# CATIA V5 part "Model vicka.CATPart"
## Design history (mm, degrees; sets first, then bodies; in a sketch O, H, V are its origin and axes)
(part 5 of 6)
    point P12 (-34.2109, 50.056)
    point P13 (-34.2607, 53.422)
    line L7 (-33.1167, 50.4591) -> (-33.1655, 53.754)
    point P15 (-33.1655, 53.754)
    line L8 (-22.1725, 60.0696) -> (-29.5056, 61.7557)
    point P16 (-29.5056, 61.7557)
    reference projected arc E12 centre (-31.265, 66.4359) radius 2 from (-32.3394, 64.749) to (-30.4134, 64.6263) ccw from edge [face of Fillet6 | face of Pad9]
    line L9 (-25.628, 55.9198) -> (-29.8107, 56.8816)
    point P17 (-25.628, 55.9198)
    point P18 (-29.8107, 56.8816)
    line L10 (-26.462, 54.9829) -> (-30.4107, 55.8909)
    point P20 (-30.4107, 55.8909)
    offset circle E13 centre (38.2049, 58.0324) radius 6.5 from edge [face of Pad47 | face of Hole7]
    offset arc E14 centre (38.2049, 58.0324) radius 6.5 from (38.8325, 51.5627) to (42.98, 53.6223) ccw from edge [face of Pad47 | face of Hole7]
    offset arc E15 centre (38.2049, 58.0324) radius 6.5 from (31.8341, 59.3221) to (32.6578, 54.6442) ccw from edge [face of Pad47 | face of Hole7]
    offset arc E16 centre (38.2049, 58.0324) radius 6.5 from (33.3151, 53.7499) to (37.7228, 51.5503) ccw from edge [face of Pad47 | face of Hole7]
    point P21 (27.2709, 56.8287)
    line L11 (27.2709, 56.8287) -> (28.9397, 54.6348)
    point P22 (28.9397, 54.6348)
    arc A2 centre (44.0622, 66.1374) radius 19 from (28.9397, 54.6348) to (30.1028, 53.2481) ccw
    point P24 (38.2983, 48.0328)
    line L12 (39.3947, 47.6838) -> (44.0557, 46.1999)
    point P25 (44.0557, 46.1999)
    reference projected arc E17 centre (34.2145, 64.9661) radius 2 from (33.2826, 63.1965) to (35.2121, 63.2327) ccw from edge [face of Fillet5 | face of Pad9]
    reference projected point E18 (38.2049, 58.0324) from Sketch44.P4
    reference projected arc E19 centre (0, 0) radius 71.425 from (68.6555, 19.6964) to (44.8942, 55.5522) ccw from edge [face of Pad1 from Sketch1.A1 | face of Pad9]
    line L13 (27.2709, 56.8287) -> (31.8341, 59.3221)
    point P26 (27.2709, 56.8287)
    point P27 (31.8341, 59.3221)
    line L14 (30.1028, 53.2481) -> (32.6578, 54.6442)
    point P29 (32.6578, 54.6442)
    line L15 (30.9032, 52.4319) -> (33.3151, 53.7499)
    point P30 (30.9032, 52.4319)
    point P31 (33.3151, 53.7499)
    line L16 (44.0557, 46.1999) -> (42.98, 53.6223)
    point P32 (42.98, 53.6223)
    line L17 (39.3947, 47.6838) -> (38.8325, 51.5627)
    point P34 (38.8325, 51.5627)
    line L18 (38.2294, 48.0549) -> (37.7228, 51.5503)
    point P35 (38.2294, 48.0549)
    point P36 (37.7228, 51.5503)
    arc A3 centre (44.0622, 66.1374) radius 19 from (30.9032, 52.4319) to (38.2294, 48.0549) ccw
    offset circle E24 centre (70.2785, -7.2128) radius 6.5 from edge [face of Pad47 | face of Hole12]
    offset arc E25 centre (70.2785, -7.2128) radius 6.5 from (64.3366, -9.8479) to (66.7122, -12.6471) ccw from edge [face of Pad47 | face of Hole12]
    offset arc E26 centre (70.2785, -7.2128) radius 6.5 from (63.9138, -5.8934) to (63.9722, -8.788) ccw from edge [face of Pad47 | face of Hole12]
    offset arc E27 centre (70.2785, -7.2128) radius 6.5 from (67.6327, -1.2757) to (64.2286, -4.8361) ccw from edge [face of Pad47 | face of Hole12]
    point P37 (64.4337, -12.9642)
    arc A4 centre (42.8563, -15.9675) radius 21.7854 from (64.4337, -12.9642) to (63.7868, -9.9244) ccw
    point P38 (42.8563, -15.9675)
    point P39 (63.627, -9.3961)
    arc A5 centre (81.742, -3.6649) radius 19 from (63.4656, -8.8585) to (62.884, -5.9837) cw
    point P41 (62.884, -5.9837)
    line L19 (62.884, -5.9837) -> (62.8445, -5.662)
    point P42 (62.1594, -0.0909)
    reference projected point E28 (70.2785, -7.2128) from Sketch44.P3
    reference projected line E29 (70.95, 8.2236) -> (75.4588, -5.0305) from edge [face of Pad47 | face of Pad6 from Sketch12.L1]
    line L20 (64.4337, -12.9642) -> (66.7122, -12.6471)
    point P43 (66.7122, -12.6471)
    line L21 (62.7023, -4.5057) -> (64.2286, -4.8361)
    point P44 (62.7023, -4.5057)
    line L22 (62.1594, -0.0909) -> (67.6327, -1.2757)
    point P46 (67.6327, -1.2757)
    line L23 (63.7868, -9.9244) -> (64.3366, -9.8479)
    point P48 (64.3366, -9.8479)
    line L24 (63.4656, -8.8585) -> (63.9722, -8.788)
    point P49 (63.4656, -8.8585)
    point P50 (63.9957, -8.7847)
    line L25 (63.9138, -5.8934) -> (62.8473, -5.6626)
    point P51 (63.9138, -5.8934)
    point P52 (62.8473, -5.6626)
    point P53 (63.9722, -8.788)
    line L26 (62.8473, -5.6626) -> (62.8445, -5.662)
    line L27 (62.7023, -4.5057) -> (62.1594, -0.0909)
    offset circle E30 centre (26.45, -66.45) radius 6.8 from edge [face of Pad47 | face of Hole11]
    offset arc E31 centre (26.45, -66.45) radius 6.8 from (26.3, -59.6517) to (21.6, -61.6837) ccw from edge [face of Pad47 | face of Hole11]
    offset arc E32 centre (26.45, -66.45) radius 6.8 from (32.3, -62.9834) to (27.3, -59.7033) ccw from edge [face of Pad47 | face of Hole11]
    line L28 (21.6, -61.6837) -> (21.6, -48.25)
    point P55 (21.6, -61.6837)
    point P56 (21.6, -48.25)
    line L29 (26.3, -59.6517) -> (26.3, -50.9964)
    point P57 (26.3, -59.6517)
    line L30 (27.3, -59.7033) -> (27.3, -51.4614)
    point P58 (27.3, -59.7033)
    line L31 (32.3, -62.9834) -> (32.3, -53.25)
    point P59 (32.3, -62.9834)
    point P60 (32.3, -53.25)
    reference projected line E33 (19.7, -73.2) -> (19.7, -54.5084) from edge [face of Pad47 | face of Pad3]
    point P61 (21.6, -48.25)
    arc A6 centre (41.5548, -19.4958) radius 35 from (21.6, -48.25) to (26.3, -50.9964) ccw
    point P63 (32.3, -53.25)
    point P64 (27.3, -51.4614)
    arc A7 centre (41.5548, -19.4958) radius 35 from (27.3, -51.4614) to (32.3, -53.25) ccw
    point P66 (63.9722, -8.788)
    distance P1 E3 = 6.7
    distance P1 E1 = 4
    distance P2 E3 = 3.6149
    length L1 = 4.2829
    radius A1 = 19
    distance E4 A1 = 3
    distance P6 E8 = 17.5
    distance P10 E8 = 19.3953
    distance P7 E9 = 11.2328
    distance P9 E10 H = 9.735
    distance P9 E10 V = 3.7831
    distance P11 E11 = 5
    distance L6 L5 = 4.4
    distance L7 L6 = 1.1
    distance P16 E12 = 3
    distance P17 P10 = 5.4
    distance L10 L9 = 1.1
    distance P17 P9 = 0.2
    radius A2 = 19
    distance P22 E17 = 9.6
    distance P21 E18 = 11
    distance P21 E19 = 8.3916
    distance E18 P25 = 13.2
    distance A2 E18 = 9
    distance P24 E18 = 10
    length L13 = 5.2
    distance P26 P21 = 0
    distance L14 L13 = 4.5
    distance L14 L15 = 1.1
    length L16 = 7.5
    distance L17 L16 = 4.4
    distance L18 L17 = 1.1
    length L12 = 4.8915
    radius A5 = 19
    distance A5 E28 = 7
    distance P42 E28 = 10.8
    distance P42 E29 = 11
    distance E28 P37 = 8.2
    distance P37 E3 = 5.7
    distance P39 E28 = 7.0006
    distance E28 P41 = 7.4959
    distance L23 L20 = 3.1
    distance L24 L23 = 1.1
    length L22 = 5.6
    distance L22 L21 = 4.2
    distance L25 L21 = 1.1
    radius A4 = 21.7854
    distance L28 E33 = 1.9
    distance L29 L28 = 4.7
    distance L30 L29 = 1
    distance L30 L31 = 5
    radius A6 = 35
    distance P60 E30 V = 20
    distance P61 P56 = 0
    distance E30 P56 V = 25
    distance P49 P50 = 0.5353
    coincidence: L2 P2, L1 P3, E1 P4, E1 P5, P11 E4, P12 A1, P13 E4, P15 E4, P16 E4, P17 A1, P18 E4, P20 E4, P26 L11, P27 E13, P29 E13, P30 A2, P31 E13, P32 E13, P34 E13, P35 A2, P36 E13, A2 A3, L20 P38, P43 E24, P44 L19, P46 E24, P48 E24, P51 E24, P52 A5, L24 P53, L19 L27, P55 E30, P57 E30, P58 E30, P59 E30, P63 P60, A6 P64, A6 A7, E24 P66, P5 P3, P4 P2, P53 P66
    tangency: A1 L3, L4 A1, A2 L11, L12 A2, A5 A4, L19 A5
    parallelism: L9 L8, L26 L25
    vertical: L28 V, L29 V, L30 V, L31 V
  Sketch120 on face of Pad47, origin (1.6, 0, 0), H (0, 1, 0), V (0, 0, 1)
    offset circle E1 centre (-26.2, -66.08) radius 6.6 from edge [face of Pad47 | face of Hole10]
    offset arc E2 centre (-26.2, -66.08) radius 6.6 from (-21.5, -61.4465) to (-25.4, -59.5287) ccw from edge [face of Pad47 | face of Hole10]
    offset arc E3 centre (-26.2, -66.08) radius 6.6 from (-26.6, -59.4922) to (-31.4, -62.0156) ccw from edge [face of Pad47 | face of Hole10]
    line L1 (-21.5, -61.4465) -> (-21.5, -52.9184)
    point P1 (-21.5, -61.4465)
    point P2 (-21.5, -52.9184)
    line L2 (-25.4, -59.5287) -> (-25.4, -55.9259)
    point P3 (-25.4, -59.5287)
    point P4 (-25.4, -55.9259)
    line L3 (-26.6, -59.4922) -> (-26.6, -56.8341)
    point P5 (-26.6, -59.4922)
    point P6 (-26.6, -56.8341)
    line L4 (-31.4, -62.0156) -> (-31.4, -58.0651)
    point P7 (-31.4, -62.0156)
    point P8 (-31.4, -58.0651)
    reference projected point E4 (-33.6, -68.8429) from vertex [face of Pocket3 | face of Pad5 from Sketch7.A1 | face of Pad47]
    reference projected line E5 (-19.7, -52.2166) -> (-19.7, -73.2) from edge [face of Pad47 | face of Pad2]
    arc A1 centre (-31.4067, -48.0651) radius 10 from (-31.4, -58.0651) to (-26.6, -56.8341) ccw
    arc A2 centre (-33.1042, -41.9028) radius 16 from (-25.4, -55.9259) to (-21.5, -52.9184) ccw
    distance E4 P8 = 11
    distance P6 E4 = 13.9
    distance P4 E4 = 15.3
    distance P2 E4 = 20
    distance L1 E5 = 1.8
    distance L2 L1 = 3.9
    distance L3 L2 = 1.2
    distance L4 L3 = 4.8
    radius A1 = 10
    radius A2 = 16
    coincidence: P1 E1, P3 E1, P5 E1, P7 E1
    vertical: L1 V, L2 V, L3 V, L4 V
  Pocket38: profile Sketch119, direction (-1, 0, 0), length 2.3
  Pocket39: profile Sketch120, direction (-1, 0, 0), length 2.3
  Sketch121 on face of Pad47, origin (1.6, 0, 0), H (0, 1, 0), V (0, 0, 1)
    offset arc E1 centre (-38.7, -63.15) radius 8 from (-30.7061, -62.8381) to (-43.1517, -56.503) ccw from edge [face of Pad47 | face of Pad10]
    offset arc E2 centre (-38.7, -63.15) radius 8 from (-31.4, -59.8774) to (-42.9711, -56.3856) ccw from edge [face of Pad47 | face of Pad10]
    arc A1 centre (-38.7, -63.15) radius 10.3 from (-29.8161, -57.9378) to (-43.2605, -53.9147) ccw
    construction line L1 (-30.7061, -62.8381) -> (-28.4085, -62.7129)
    construction line L2 (-43.1517, -56.503) -> (-44.4316, -54.592)
    offset line E3 (-42.7198, -56.7539) -> (-43.7073, -55.3064) from edge [face of Pad47 | face of Pad4 from Sketch6.L2]
    offset line E4 (-42.9711, -56.3856) -> (-43.7073, -55.3064) from edge [face of Pad47 | face of Pad4 from Sketch6.L2]
    offset arc E5 centre (-44.9464, -56.1518) radius 1.5 from (-43.7073, -55.3064) to (-44.0091, -54.9808) ccw from edge [face of Fillet2 | face of Pad47]
    point P9 (-41.8074, -54.0102)
    offset arc E6 centre (0, 0) radius 70.425 from (-70.1352, 6.382) to (-44.0091, -54.9808) ccw from edge [face of Pad1 from Sketch1.A1 | face of Pad47]
    offset arc E7 centre (0, 0) radius 69.125 from (-68.8406, 6.2642) to (-43.1967, -53.9658) ccw from edge [face of Pad1 from Sketch1.A1 | face of Pad47]
    offset arc E8 centre (0, 0) radius 69.125 from (-68.8406, 6.2642) to (-43.2605, -53.9147) ccw from edge [face of Pad1 from Sketch1.A1 | face of Pad47]
    arc A2 centre (-69.4879, 6.3231) radius 0.65 from (-70.1352, 6.382) to (-68.8406, 6.2642) cw
    point P15 (-43.2605, -53.9147)
    point P16 (-42.9711, -56.3856)
    point P17 (-42.9711, -56.3856)
    projected line E9 (-31.4, -58.0651) -> (-31.4, -62.0156) from edge [face of Pad47 | face of Pocket39 from Sketch120.L4]
    projected line E10 (-31.4, -58.0651) -> (-31.4, -59.8774) from edge [face of Pad47 | face of Pocket39 from Sketch120.L4]
    projected arc E11 centre (-31.4067, -48.0651) radius 10 from (-31.4, -58.0651) to (-26.6, -56.8341) ccw from edge [face of Pad47 | face of Pocket39 from Sketch120.A1]
    projected arc E12 centre (-31.4067, -48.0651) radius 10 from (-31.4, -58.0651) to (-29.8161, -57.9378) ccw from edge [face of Pad47 | face of Pocket39 from Sketch120.A1]
    point P22 (-29.8161, -57.9378)
    point P23 (-31.4, -59.8774)
    point P24 (-31.4, -59.8774)
    point P25 (-29.8161, -57.9378)
    point P26 (-65.1735, 18.7249)
    line L3 (-65.1735, 18.7249) -> (-59.997, 26.0872)
    arc A3 centre (-96.8086, 51.9698) radius 45 from (-59.997, 26.0872) to (-54.8919, 35.5993) ccw
    point P29 (-54.8919, 35.5993)
    line L4 (-54.8919, 35.5993) -> (-38.6712, 54.0939)
    point P30 (-38.6712, 54.0939)
    reference projected point E13 (-65.1735, 18.7249) from vertex [face of Pocket38 from Sketch119.L2 | face of Pocket38 from Sketch119.E2 | face of Pad47]
    reference projected point E14 (-38.6712, 54.0939) from vertex [face of Pocket38 from Sketch119.L5 | face of Pocket38 from Sketch119.E7 | face of Pad47]
    reference projected circle E15 centre (0, 0) radius 71.425 from edge [face of Pad1 from Sketch1.A1 | face of Pad47]
    line L5 (-61.291, 20.8391) -> (-58.3937, 24.9599)
    point P32 (-58.3937, 24.9599)
    construction line L6 (-65.1735, 18.7249) -> (-63.5702, 17.5975)
    construction line L7 (-59.997, 26.0872) -> (-58.3937, 24.9599)
    arc A4 centre (-95.2052, 50.8425) radius 45 from (-58.3937, 24.9599) to (-54.7989, 31.0351) ccw
    point P33 (-58.3937, 24.9599)
    point P34 (-54.7989, 31.0351)
    point P35 (-58.3937, 24.9599)
    line L8 (-51.7449, 36.1998) -> (-38.6277, 51.1559)
    construction line L9 (-54.8919, 35.5993) -> (-53.4108, 34.3004)
    construction line L10 (-38.6712, 54.0939) -> (-37.1901, 52.7949)
    line L11 (-54.7989, 31.0351) -> (-51.7449, 36.1998)
    reference projected arc E16 centre (-68.2522, 13.0002) radius 6.5 from (-63.1114, 16.9779) to (-65.1735, 18.7249) ccw from edge [face of Pad47 | face of Pocket38 from Sketch119.E2]
    projected line E17 (-61.2757, 20.8474) -> (-65.1735, 18.7249) from edge [face of Pad47 | face of Pocket38 from Sketch119.L2]
    projected line E18 (-61.291, 20.8391) -> (-65.1735, 18.7249) from edge [face of Pad47 | face of Pocket38 from Sketch119.L2]
    projected line E19 (-38.6712, 54.0939) -> (-38.5897, 48.5938) from edge [face of Pad47 | face of Pocket38 from Sketch119.L5]
    projected line E20 (-38.6712, 54.0939) -> (-38.6277, 51.1559) from edge [face of Pad47 | face of Pocket38 from Sketch119.L5]
    point P43 (-38.6277, 51.1559)
    point P44 (-61.291, 20.8391)
    point P45 (4.5944, 65.5788)
    line L12 (4.5944, 65.5788) -> (-13.3822, 66.4964)
    arc A5 centre (-13.9429, 55.5107) radius 11 from (-13.3822, 66.4964) to (-17.5476, 65.9033) ccw
    line L13 (-17.5476, 65.9033) -> (-29.5056, 61.7557)
    point P49 (-29.5056, 61.7557)
    projected line E21 (-22.1725, 60.0696) -> (-29.5056, 61.7557) from edge [face of Pad47 | face of Pocket38 from Sketch119.L8]
    projected line E22 (-26.5819, 61.0834) -> (-29.5056, 61.7557) from edge [face of Pad47 | face of Pocket38 from Sketch119.L8]
    point P51 (-29.5056, 61.7557)
    point P52 (12.3014, 65.1854)
    line L14 (12.3014, 65.1854) -> (31.8341, 59.3221)
    point P53 (31.8341, 59.3221)
    point P54 (31.8341, 59.3221)
    projected line E23 (31.8341, 59.3221) -> (27.2709, 56.8287) from edge [face of Pad47 | face of Pocket38 from Sketch119.L13]
    projected line E24 (31.8341, 59.3221) -> (28.324, 57.4041) from edge [face of Pad47 | face of Pocket38 from Sketch119.L13]
    point P55 (31.8341, 59.3221)
    point P57 (-26.5819, 61.0834)
    line L15 (-26.5819, 61.0834) -> (-16.5856, 63.6927)
    arc A6 centre (-11.5344, 44.3411) radius 20 from (-16.5856, 63.6927) to (-10.2511, 64.2999) cw
    line L16 (-10.2511, 64.2999) -> (5.7159, 63.2732)
    arc A7 centre (2.4436, 12.3783) radius 51 from (5.7159, 63.2732) to (19.053, 60.5979) cw
    line L17 (19.053, 60.5979) -> (28.324, 57.4041)
    point P64 (28.324, 57.4041)
    reference projected arc E25 centre (0, 0) radius 71.425 from (68.6555, 19.6964) to (44.8942, 55.5522) ccw from edge [face of Pad1 from Sketch1.A1 | face of Pad9]
    projected arc E30 centre (8.6256, 68.8636) radius 5.2 from (4.0374, 71.3108) to (13.6756, 70.1036) ccw from edge [face of Pocket29 from Sketch77.A1 | end face of Pocket29]
    projected arc E31 centre (8.6256, 68.8636) radius 5.2 from (4.5944, 65.5788) to (12.3014, 65.1854) ccw from edge [face of Pocket29 from Sketch77.A1 | end face of Pocket29]
    point P67 (4.5944, 65.5788)
    line L18 (43.2555, 51.7213) -> (46.5715, 46.7209)
    point P68 (46.5715, 46.7209)
    arc A8 centre (55.0103, 52.3169) radius 10.1257 from (46.5715, 46.7209) to (49.4386, 43.862) ccw
    point P70 (49.4386, 43.862)
    offset arc E32 centre (-26.1946, -18.2866) radius 97.8919 from (69.6836, 1.4667) to (41.3732, 52.5471) ccw from edge [face of Pocket8 from Sketch18.A16 | end face of Pocket8]
    offset arc E33 centre (-26.1946, -18.2866) radius 97.8919 from (60.1421, 27.8525) to (49.4386, 43.862) ccw from edge [face of Pocket8 from Sketch18.A16 | end face of Pocket8]
    arc A9 centre (-35.6326, -0.9089) radius 100 from (60.1421, 27.8525) to (63.95, 8.2183) cw
    point P73 (-35.6326, -0.9089)
    point P74 (60.1421, 27.8525)
    point P75 (63.95, 8.2183)
    reference projected line E34 (67.6327, -1.2757) -> (62.1594, -0.0909) from edge [face of Pad47 | face of Pocket38 from Sketch119.L22]
    reference projected point E35 (70.95, 8.2236) from vertex [face of Pad6 | face of Pad6 from Sketch12.L1 | face of Pocket7 from Sketch13.A1]
    projected line E36 (44.0557, 46.1999) -> (42.98, 53.6223) from edge [face of Pad47 | face of Pocket38 from Sketch119.L16]
    projected line E37 (43.7295, 48.4511) -> (43.2555, 51.7213) from edge [face of Pad47 | face of Pocket38 from Sketch119.L16]
    point P78 (43.2555, 51.7213)
    reference projected arc E38 centre (0, 0) radius 71.425 from (34.7, -62.4295) to (69.95, -14.4405) ccw from edge [face of Pad1 from Sketch1.A1 | face of Pad47]
    arc A10 centre (-35.6326, -0.9089) radius 98.5 from (62.4563, 8.0814) to (58.7054, 27.421) ccw
    point P80 (58.7054, 27.421)
    construction line L19 (63.95, 8.2183) -> (62.4563, 8.0814)
    construction line L20 (60.1421, 27.8525) -> (58.7054, 27.421)
    arc A11 centre (-26.2144, -18.2498) radius 96.422 from (58.7054, 27.421) to (48.328, 42.9109) ccw
    point P81 (48.328, 42.9109)
    point P82 (58.7054, 27.421)
    arc A12 centre (55.0103, 52.3169) radius 11.538 from (45.3944, 45.9403) to (48.328, 42.9109) ccw
    point P83 (45.3944, 45.9403)
    point P84 (48.328, 42.9109)
    line L21 (43.7295, 48.4511) -> (45.3944, 45.9403)
    point P86 (45.3944, 45.9403)
    construction line L22 (43.2555, 51.7213) -> (42.0785, 50.9407)
    construction line L23 (46.5715, 46.7209) -> (45.3944, 45.9403)
    point P87 (45.3944, 45.9403)
    arc A13 centre (63.2031, 8.1499) radius 0.75 from (62.4563, 8.0814) to (63.95, 8.2183) ccw
    point P89 (43.7295, 48.4511)
    point P90 (43.2555, 51.7213)
    point P91 (67.3486, -14.657)
    line L24 (67.3486, -14.657) -> (66.7542, -16.0342)
    arc A14 centre (79.6084, -21.5813) radius 14 from (66.7542, -16.0342) to (65.6168, -21.0972) ccw
    point P94 (65.6168, -21.0972)
    arc A15 centre (49.6264, -20.544) radius 16 from (65.6168, -21.0972) to (61.6888, -31.0558) cw
    line L25 (61.6888, -31.0558) -> (38.2804, -57.9176)
    point P97 (38.2804, -57.9176)
    arc A16 centre (-14.493, -11.9287) radius 70 from (38.2804, -57.9176) to (33.8965, -62.5099) cw
    point P99 (33.8965, -62.5099)
    reference projected circle E40 centre (70.2785, -7.2128) radius 5 from edge [face of Pad9 | face of Hole12]
    line L26 (65.5123, -13.8645) -> (64.9179, -15.2418)
    point P101 (64.9179, -15.2418)
    construction line L27 (67.3486, -14.657) -> (65.5123, -13.8645)
    construction line L28 (66.7542, -16.0342) -> (64.9179, -15.2418)
    arc A17 centre (79.6084, -21.5813) radius 16 from (64.9179, -15.2418) to (63.618, -21.0281) ccw
    point P103 (63.618, -21.0281)
    arc A18 centre (49.6264, -20.544) radius 14 from (60.181, -29.7418) to (63.618, -21.0281) ccw
    point P104 (60.181, -29.7418)
    point P105 (63.618, -21.0281)
    point P106 (63.618, -21.0281)
    line L29 (60.181, -29.7418) -> (36.7726, -56.6036)
    point P108 (36.7726, -56.6036)
    construction line L30 (61.6888, -31.0558) -> (60.181, -29.7418)
    construction line L31 (38.2804, -57.9176) -> (36.7726, -56.6036)
    point P109 (60.181, -29.7418)
    arc A19 centre (-14.493, -11.9287) radius 68 from (32.5139, -61.0647) to (36.7726, -56.6036) ccw
    point P111 (36.7726, -56.6036)
    point P112 (36.7726, -56.6036)
    arc A20 centre (66.4304, -14.2607) radius 1 from (67.3486, -14.657) to (65.5123, -13.8645) ccw
    point P113 (66.4304, -14.2607)
    arc A21 centre (33.2052, -61.7873) radius 1 from (32.5139, -61.0647) to (33.8965, -62.5099) ccw
    point P114 (33.2052, -61.7873)
    point P115 (32.5139, -61.0648)
    reference projected point E41 (32.3, -62.9834) from vertex [face of Pocket38 from Sketch119.L31 | face of Pocket38 from Sketch119.E32 | face of Pad47]
    distance E1 A1 = 2.3
    distance P26 E13 = 0
    distance P30 E14 = 0
    length L3 = 9
    radius A3 = 45
    length L4 = 24.6
    distance P29 E15 = 6
    distance L3 L5 = 1.96
    distance L4 L8 = 1.97
    length L11 = 6
    radius A4 = 45
    distance P34 E16 = 16
    distance P49 P51 = 0
    distance A5 E25 = 3.19
    radius A5 = 11
    angle L13 L15 = 4.5
    distance P57 P49 = 3
    length L15 = 10.3312
    length L13 = 12.6569
    length L12 = 18
    radius A6 = 20
    length L16 = 16
    radius A7 = 51
    distance P53 P54 = 0
    distance P64 P53 = 4
    distance P53 P55 = 0
    distance P45 E30 = 0
    radius A9 = 100
    distance P75 E34 = 8.5
    distance P75 P74 = 20
    distance P75 E35 = 7
    radius A8 = 10.1257
    distance P78 E38 = 4
    distance P68 P78 = 6
    distance P70 P78 = 10
    distance A9 A10 = 1.5
    distance L18 L21 = 1.4123
    radius A11 = 96.422
    radius A12 = 11.538
    distance P81 P89 = 7.2
    distance P91 E40 = 3
    length L24 = 1.5
    radius A14 = 14
    radius A15 = 16
    distance P91 E15 = 2.5
    distance P94 E15 = 2.5
    length L25 = 35.6302
    distance P97 E15 = 2
    radius A16 = 70
    distance L24 L26 = 2
    distance L25 L29 = 2
    radius A19 = 68
    radius A18 = 14
    radius A17 = 16
    distance P103 P101 = 5.9305
    distance P103 P104 = 9.3671
    distance P113 P91 = 1
    distance P114 P99 = 1
    distance A21 E41 = 2.5
    concentricity: E1 A1, A9 A10
    tangency: E5 E3, E6 E5, A2 E6, A3 L3, A4 L5, A5 L12, A5 L13, A6 L15, L16 A6, A7 L16, A7 L17, A8 L18, L21 A12, A13 A10, L24 A9, A14 L24, A15 A14, L25 A15, A16 L25, A17 L26, A18 A17, A19 L29
    coincidence: E7 P15, E3 P16, E1 P17, A1 P22, E1 P23, E9 P24, E11 P25, P33 P32, A4 P35, P35 P32, E19 P43, E17 P44, P52 L12, P57 E21, P64 E23, L17 P45, L12 P67, E32 P70, P74 E32, E36 P78, L19 P73, L20 P73, A11 P82, P82 P80, A12 P84, P84 P81, P86 P83, L21 P87, P87 P83, E36 P89, L18 P90, P105 P103, A18 P106, P106 P103, L29 P109, P109 A18, L29 P104, P111 P108, A19 P112, P112 P108, A21 P115, P115 A19, P16 P17, P22 P25, P23 P24, P78 P90
    perpendicularity: L6 L3, L6 L5, L7 L3, L7 L5, L9 L4, L9 L8, L10 L4, L10 L8, L22 L18, L22 L21, L23 L18, L23 L21, L27 L24, L27 L26, L28 L24, L28 L26, L30 L25, L30 L29, L31 L25, L31 L29
  Pocket40: profile Sketch121, direction (-1, 0, 0), length 0.5
  Sketch122 on face of Pad47, origin (1.6, 0, 0), H (0, 1, 0), V (0, 0, 1)
  Pad48: profile Sketch122, direction (1, 0, 0), length 1
  Plane8: type Offset, RefPlane xy-plane, Offset 0.375
  Sketch123 on Plane8, origin (0, 0, 0.375), H (1, 0, 0), V (0, 1, 0)
    projected line E1 (1.6, 2.8785) -> (-1.4, 2.8785) from edge [face of Pocket12 | face of Pocket12]
    projected line E2 (-2.9, 2.8785) -> (-1.4, 2.8785) from edge [face of Fillet17 | face of Pocket12]
    projected line E3 (1.6, -23.1215) -> (1.6, 2.8785) from edge [face of Fillet18 | face of Pad47]
    projected line E4 (1.6, -23.1215) -> (-1.4, -23.1215) from edge [face of Pocket12 | face of Pocket12]
    projected line E5 (-1.4, -23.1215) -> (-2.9, -23.1215) from edge [face of Fillet17 | face of Pocket12]
    projected line E6 (-2.9, 2.8785) -> (-2.9, -23.1215) from edge [face of Pocket12 | end face of Pocket12]
  Pad49: profile Sketch123, direction (0, 0, 1), up to the existing solid (limit type 2)
  Mirror2: of Pad49, about Plane2
  Sketch124 on face of Pad47, origin (1.6, 0, 0), H (0, 1, 0), V (0, 0, 1)
    line L1 (-23.1215, 12.6747) -> (-17.5965, 12.6747)
    line L2 (-17.5965, 12.6747) -> (-17.5965, 8.0747)
    line L3 (-17.5965, 8.0747) -> (-23.1215, 8.0747)
    line L4 (-23.1215, 8.0747) -> (-23.1215, 12.6747)
    line L5 (-16.2965, 12.6747) -> (-10.7715, 12.6747)
    line L6 (-10.7715, 12.6747) -> (-10.7715, 8.0747)
    line L7 (-10.7715, 8.0747) -> (-16.2965, 8.0747)
    line L8 (-16.2965, 8.0747) -> (-16.2965, 12.6747)
    point P7 (-10.7715, 8.0747)
    point P9 (-9.4715, 12.6747)
    line L9 (-9.4715, 12.6747) -> (-3.9465, 12.6747)
    line L10 (-3.9465, 12.6747) -> (-3.9465, 8.0747)
    line L11 (-3.9465, 8.0747) -> (-9.4715, 8.0747)
    line L12 (-9.4715, 8.0747) -> (-9.4715, 12.6747)
    line L13 (-2.6465, 12.6747) -> (2.8785, 12.6747)
    line L14 (2.8785, 12.6747) -> (2.8785, 8.0747)
    line L15 (2.8785, 8.0747) -> (-2.6465, 8.0747)
    line L16 (-2.6465, 8.0747) -> (-2.6465, 12.6747)
    point P15 (2.8785, 8.0747)
    reference projected line E1 (-23.1215, 13.8747) -> (2.8785, 13.8747) from edge [face of Pad47 | face of Mirror2]
    reference projected line E2 (-23.1215, 17.6747) -> (-23.1215, 10.3747) from edge [face of Pad47 | face of Pocket12]
    distance L1 E1 = 1.2
    distance L4 E2 = 0
    length L4 = 4.6
    length L3 = 5.525
    distance L2 L8 = 1.3
    distance L5 E1 = 1.2
    length L7 = 5.525
    distance L12 L6 = 1.3
    length L11 = 5.525
    length L12 = 4.6
    distance L16 L10 = 1.3
    distance L13 E1 = 1.2
    length L13 = 5.525
    horizontal: L1 H, L3 H, L5 H, L7 H, L9 H, L11 H, L13 H, L15 H
    vertical: L2 V, L4 V, L6 V, L8 V, L10 V, L12 V, L14 V, L16 V
    coincidence: P7 L3, P9 L5, P15 L3
  Pocket41: profile Sketch124, direction (-1, 0, 0), length 0.5
  Mirror3: of Pocket41, about Plane2
  Sketch125 on end face of Pad48, origin (2.6, 0, 0), H (0, 1, 0), V (0, 0, 1)
    projected line E1 (59.4116, -23.26) -> (50.3961, -25.2175) from edge [face of Pad48 | end face of Pad48]
    point P2 (50.3961, -25.2175)
    projected arc E2 centre (32.0116, -10.7803) radius 30.1082 from (55.0696, -30.1408) to (59.4116, -23.26) ccw from edge [face of Pad48 | end face of Pad48]
    line L1 (55.0696, -30.1408) -> (50.3961, -25.2175)
    point P5 (55.0696, -30.1408)
    point P6 (50.3961, -25.2175)
    length L1 = 6.7883
    coincidence: P5 E2, P6 E1, L1 P2
  Pocket42: profile Sketch125, direction (-1, 0, 0), length 1
  Fillet48: radius 0.1, on edge [face of Pocket42 | face of Pocket40 from Sketch121.A19]; edge [face of Pocket42 | face of Pocket40 from Sketch121.L29]
  Fillet49: radius 0.1, on edge [face of Pocket38 from Sketch119.L31 | face of Pocket38 from Sketch119.E32]; edge [face of Pocket42 | face of Pocket38 from Sketch119.L31] (x2); edge [face of Pocket38 from Sketch119.L31 | face of Fillet48] (x2); edge [face of Pocket38 from Sketch119.L31 | end face of Pocket40]; edge [face of Pocket40 from Sketch121.A21 | face of Pocket38 from Sketch119.L31]; edge [face of Pocket42 | face of Pocket38 from Sketch119.A7]; edge [face of Pocket42 | face of Pocket38 from Sketch119.L30]; edge [face of Pocket42 | face of Pocket38 from Sketch119.E32] (x2); edge [face of Pocket38 from Sketch119.E32 | end face of Pocket38] (x2); edge [face of Pocket38 from Sketch119.L31 | end face of Pocket38]; edge [face of Pocket38 from Sketch119.A7 | end face of Pocket38]; edge [face of Pocket38 from Sketch119.L30 | end face of Pocket38]; edge [face of Pocket38 from Sketch119.E32 | face of Pocket38 from Sketch119.L30]; edge [face of Pocket38 from Sketch119.L30 | face of Pocket38 from Sketch119.A7]; face of Pocket38 from Sketch119.A7; edge [face of Pocket38 from Sketch119.L29 | face of Pocket38 from Sketch119.E32]; edge [face of Pocket42 | face of Pocket38 from Sketch119.L29]; edge [face of Pocket38 from Sketch119.L29 | end face of Pocket38]; face of Pocket38 from Sketch119.E32; edge [face of Pocket42 | face of Pocket38 from Sketch119.L28]; edge [face of Pocket42 | face of Pocket38 from Sketch119.A6]; edge [face of Pocket38 from Sketch119.A6 | face of Pocket38 from Sketch119.L29]; face of Pocket38 from Sketch119.L28; end face of Pocket38
  Fillet50: radius 0.1, on edge [face of Pocket42 | face of Slot1]; face of Slot1 (x11); face of Pad32 from Sketch83.L4; face of Pad32 from Sketch83.L3; face of Pad32 from Sketch83.L2; face of Chamfer26; face of Pad32 from Sketch83.L1
  Fillet51: radius 0.1, on edge [face of Pocket42 | face of Pocket40 from Sketch121.A1]; edge [face of Pocket40 from Sketch121.A1 | end face of Pocket40]; edge [face of Pocket40 from Sketch121.E2 | end face of Pocket40]; edge [face of Pocket42 | face of Pocket40 from Sketch121.E2]; edge [face of Pocket40 from Sketch121.E4 | end face of Pocket40]; edge [face of Pocket40 from Sketch121.E6 | end face of Pocket40]; edge [face of Pocket40 from Sketch121.E5 | end face of Pocket40]; edge [face of Pocket42 | face of Pocket40 from Sketch121.E5]; edge [face of Pocket42 | face of Pocket40 from Sketch121.E4]; edge [face of Pocket42 | face of Pocket40 from Sketch121.E6]
  Fillet52: radius 0.1, on face of Slot4 (x4); face of Pad47 from Sketch118.L1
  Fillet53: radius 0.2, on edge [face of Slot4 | face of Chamfer31]; face of Chamfer31
  Fillet54: radius 0.2, on edge [face of Pad47 from Sketch118.L3 | face of Slot4]; edge [face of Slot4 | face of Pad47 from Sketch118.L3]
  Fillet55: radius 0.2, on edge [face of Pad47 from Sketch118.L2 | face of Slot4]
  Fillet56: radius 0.1, on edge [face of Pocket42 | face of Pocket40 from Sketch121.L3]
  Fillet57: radius 0.1, on edge [face of Pocket40 from Sketch121.L5 | end face of Pocket40]
  Fillet58: radius 0.1, on edge [face of Pocket40 from Sketch121.L11 | end face of Pocket40]
  Fillet59: radius 0.1, on edge [face of Pocket40 from Sketch121.L8 | end face of Pocket40]; edge [face of Pocket40 from Sketch121.L4 | end face of Pocket40]; edge [face of Pocket42 | face of Pocket40 from Sketch121.L4]; edge [face of Pocket42 | face of Pocket40 from Sketch121.L8]; edge [face of Pocket42 | face of Pocket40 from Sketch121.L11]
  Fillet60: radius 0.3, on edge [face of Slot2 | face of Slot2] (x2)
  Fillet61: radius 0.6, on edge [face of Slot2 | face of Slot2]
  Chamfer32: length 2, angle 26.5, on edge [end face of Pad48 | face of Pocket42 from Sketch125.L1]
  Sketch126 on end face of Pad48, origin (2.6, 0, 0), H (0, 1, 0), V (0, 0, 1)
    projected line E1 (21.9698, -38.86) -> (19.7248, -42.6309) from edge [face of Pad48 | end face of Pad48]
    line L1 (21.9698, -38.86) -> (22.8291, -39.3716)
    line L2 (22.8291, -39.3716) -> (20.584, -43.1424)
    point P4 (20.584, -43.1424)
    line L3 (20.584, -43.1424) -> (19.7248, -42.6309)
    point P5 (20.584, -43.1424)
    length L1 = 1
    perpendicularity: L1 E1, L3 E1
    parallelism: L2 E1
    coincidence: P5 L2, P4 P5
  Pocket43: profile Sketch126, direction (-1, 0, 0), length 1
  Chamfer33: length 2, angle 26.5, on edge [end face of Pad48 | face of Pocket43 from Sketch126.L2]
  Fillet62: radius 0.1, on edge [face of Pad47 from Sketch118.L4 | face of Slot3]; edge [face of Slot3 | face of Pad47 from Sketch118.L4]; edge [face of Pad47 from Sketch118.L5 | face of Slot3]; edge [face of Slot3 | face of Pad47 from Sketch118.L5]
  Fillet63: radius 0.1, on face of Slot5
  Fillet64: radius 0.1, on face of Pad47 from Sketch118.L6; face of Slot5; face of Slot3 (x4); face of Pad46 from Sketch117.L12
  Fillet65: radius 0.1, on face of Slot5; face of Pad46 from Sketch117.L11; face of Slot3 (x2); face of Pad46 from Sketch117.L10
  Fillet66: radius 0.1, on edge [face of Pad46 from Sketch117.L9 | face of Slot3] (x2); edge [face of Pad46 from Sketch117.L8 | face of Slot3]
  Fillet67: radius 0.1, on edge [face of Slot3 | face of Pad46 from Sketch117.L8]
  Fillet68: radius 0.1, on edge [face of Slot3 | face of Pocket43] (x2); edge [face of Pocket43 | face of Slot3] (x2); edge [face of Pad46 from Sketch117.L9 | face of Pocket43]
  Fillet69: radius 0.1, on face of Slot5
  Fillet70: radius 0.1, on face of Slot5; face of Slot3 (x2); face of Pad46 from Sketch117.L6; face of Pad46 from Sketch117.L7
  Fillet71: radius 0.1, on face of Slot5 (x2); face of Slot3 (x2); face of Chamfer28; face of Slot6; face of Pad34 from Sketch96.L2; face of Pad46 from Sketch117.L5
  Fillet72: radius 0.1, on face of Slot6; face of Fillet38
  Fillet73: radius 0.5, on edge [face of Pocket38 from Sketch119.E2 | face of Pocket38 from Sketch119.L2]; edge [face of Pocket38 from Sketch119.L1 | face of Pocket38 from Sketch119.E2]; edge [face of Pocket38 from Sketch119.L2 | face of Pocket38 from Sketch119.L1]
  Fillet74: radius 1, on edge [face of Pocket38 from Sketch119.E2 | face of Pocket40 from Sketch121.L3]
  Fillet75: radius 0.1, on edge [face of Slot7 | face of Slot7] (x2)
  Fillet76: radius 0.1, on edge [face of Slot7 | face of Pad46 from Sketch117.L4] (x2); edge [face of Slot7 | face of Slot7] (x2); edge [face of Slot7 | face of Pad33 from Sketch95.L2]; edge [face of Pad33 from Sketch95.L2 | face of Slot7]
  Fillet77: radius 0.1, on face of Pocket33; edge [face of Pocket43 | face of Slot7]
  Fillet78: radius 0.1, on edge [face of Slot7 | face of Slot7]
  Fillet79: radius 0.1, on face of Pocket33
  Fillet80: radius 0.1, on edge [face of Pad46 from Sketch117.L3 | face of Slot7] (x2); edge [face of Slot7 | face of Pad46 from Sketch117.L2]; edge [face of Pad46 from Sketch117.L2 | face of Slot7]
  Fillet81: radius 0.1, on edge [face of Slot7 | face of Pocket43]
  Fillet82: radius 0.1, on face of Pocket33; face of Slot7 (x3); face of Pad46 from Sketch117.L1; face of Pad45 from Sketch116.L6
  Fillet83: radius 0.1, on face of Slot7 (x11); face of Pad45 from Sketch116.L5; face of Pocket33 (x3); face of Pad45 from Sketch116.L4; face of Pad45 from Sketch116.L3; face of Pad45 from Sketch116.L2; face of Pad45 from Sketch116.L1; edge [face of Pad44 from Sketch115.L2 | face of Pocket43]
  Fillet84: radius 0.1, on face of Slot7 (x4); face of Pocket33; edge [face of Slot7 | face of Slot7]; face of Pad44 from Sketch115.L1; face of Pad37 from Sketch107.L1
  Fillet85: radius 0.1, on edge [face of Pad38 from Sketch108.E5 | face of Fillet46]
  Fillet86: radius 0.1, on edge [face of Slot8 | face of Pad35]
  Fillet87: radius 0.03, on edge [face of Pocket43 | face of Pad35]
  Fillet88: radius 0.03, on edge [face of Pad38 from Sketch108.E12 | face of Slot8]
  Fillet89: radius 0.03, on edge [face of Pocket43 | face of Pad39 from Sketch110.L1]
  Fillet90: radius 0.6, on edge [face of Slot8 | face of Slot8] (x2)
  Fillet91: radius 0.5, on edge [face of Slot8 | face of Slot8]
  Fillet92: radius 0.1, on edge [face of Slot8 | face of Slot8] (x2); edge [face of Pad42 from Sketch113.L2 | face of Slot8]
  Fillet93: radius 0.1, on edge [face of Slot8 | face of Slot8]
  Fillet94: radius 0.1, on edge [face of Slot8 | face of Slot8]
  Fillet95: radius 0.6, on edge [face of Slot8 | face of Slot8] (x2)
  Fillet96: radius 0.5, on edge [face of Pocket38 from Sketch119.L8 | face of Pocket38 from Sketch119.L4]; edge [face of Pocket38 from Sketch119.L4 | face of Pocket38 from Sketch119.L9]; edge [face of Pocket38 from Sketch119.L9 | face of Pocket38 from Sketch119.E7]; edge [face of Pocket38 from Sketch119.E7 | face of Pocket38 from Sketch119.L8]; edge [face of Pocket38 from Sketch119.E7 | face of Pocket40 from Sketch121.L13]; edge [face of Pocket38 from Sketch119.E7 | face of Pocket38 from Sketch119.L10]; edge [face of Pocket38 from Sketch119.L10 | face of Pocket38 from Sketch119.A1]; edge [face of Pocket38 from Sketch119.A1 | face of Pocket38 from Sketch119.L7]; edge [face of Pocket38 from Sketch119.L7 | face of Pocket38 from Sketch119.E7]; edge [face of Pocket38 from Sketch119.E7 | face of Pocket38 from Sketch119.L6]; edge [face of Pocket38 from Sketch119.L5 | face of Pocket38 from Sketch119.E7]; edge [face of Pocket40 from Sketch121.L4 | face of Pocket38 from Sketch119.E7]; edge [face of Pocket38 from Sketch119.L3 | face of Pocket38 from Sketch119.L5]; edge [face of Pocket38 from Sketch119.L6 | face of Pocket38 from Sketch119.L3]
  Fillet97: radius 0.1, on edge [face of Pocket43 | face of Pocket40 from Sketch121.A4]; edge [face of Pocket40 from Sketch121.L5 | face of Pocket43]
  Fillet98: radius 0.5, on edge [face of Pocket38 from Sketch119.E16 | face of Pocket38 from Sketch119.L14]; edge [face of Pocket38 from Sketch119.L13 | face of Pocket38 from Sketch119.E16]; edge [face of Pocket40 from Sketch121.L14 | face of Pocket38 from Sketch119.E16]; edge [face of Pocket38 from Sketch119.L11 | face of Pocket38 from Sketch119.L13]; edge [face of Pocket38 from Sketch119.L14 | face of Pocket38 from Sketch119.A2]; edge [face of Pocket38 from Sketch119.L15 | face of Pocket38 from Sketch119.E16]; edge [face of Pocket38 from Sketch119.A3 | face of Pocket38 from Sketch119.L15]; edge [face of Pocket38 from Sketch119.L18 | face of Pocket38 from Sketch119.A3]; edge [face of Pocket38 from Sketch119.E16 | face of Pocket38 from Sketch119.L18]; edge [face of Pocket38 from Sketch119.L17 | face of Pocket38 from Sketch119.E16]; edge [face of Pocket38 from Sketch119.E16 | face of Pocket38 from Sketch119.L16]; edge [face of Pocket38 from Sketch119.L16 | face of Pocket38 from Sketch119.L12]
  Fillet99: radius 0.6, on edge [face of Slot8 | face of Slot8]
  Fillet100: radius 0.1, on edge [face of Pocket43 | face of Slot8] (x7); edge [face of Pad39 from Sketch110.L2 | face of Pocket43]; edge [face of Slot8 | face of Pocket43] (x5); edge [face of Pad43 from Sketch114.L2 | face of Pocket43]; edge [face of Pad43 from Sketch114.L1 | face of Pocket43]; edge [face of Pad42 from Sketch113.L1 | face of Pocket43]; edge [face of Pad42 from Sketch113.L2 | face of Pocket43]; edge [face of Fillet99 | face of Pocket43]; edge [face of Pad41 from Sketch112.L2 | face of Pocket43]; edge [face of Pad41 from Sketch112.L1 | face of Pocket43]; edge [face of Pad40 from Sketch111.L2 | face of Pocket43]; edge [face of Pad40 from Sketch111.L1 | face of Pocket43]
  Fillet101: radius 0.5, on end face of Pocket12; edge [face of Pad29 from Sketch61.A1 | face of Pad30]; edge [face of Pocket43 | face of Pocket12] (x7); edge [face of Pocket43 | face of Mirror2]; edge [face of Pocket12 | face of Mirror2] (x2); edge [face of Pocket12 | end face of Pocket12]; face of Pocket12 (x4); face of Mirror2; start face of Pad49; edge [face of Pocket12 | face of Pocket12] (x4)
  Fillet102: radius 0.5, on edge [face of Pocket39 from Sketch120.L1 | face of Pocket39 from Sketch120.E3]; edge [face of Pocket39 from Sketch120.A2 | face of Pocket39 from Sketch120.L1]; edge [face of Pocket39 from Sketch120.L2 | face of Pocket39 from Sketch120.A2]; edge [face of Pocket39 from Sketch120.E3 | face of Pocket39 from Sketch120.L2]; edge [face of Pocket39 from Sketch120.A1 | face of Pocket39 from Sketch120.L3]; edge [face of Pocket39 from Sketch120.L3 | face of Pocket39 from Sketch120.E3]; edge [face of Pocket39 from Sketch120.E3 | face of Pocket39 from Sketch120.L4]; edge [face of Pocket39 from Sketch120.L4 | face of Pocket39 from Sketch120.A1]
  Sketch127 on face of Pad9, origin (0, 0, 0), H (0, -1, 0), V (0, 0, 1)
    projected line E1 (31.75, -62.8) -> (31.7053, -62.8771) from edge [face of Pad5 from Sketch7.L2 | face of Pad9]
    projected arc E2 centre (39.7026, -63.67) radius 8 from (31.75, -62.8) to (31.7059, -63.4379) ccw from edge [face of Pad5 from Sketch7.A1 | face of Pad9]
    projected arc E3 centre (38.7, -63.15) radius 7 from (31.7053, -62.8771) to (31.7059, -63.4379) ccw from edge [face of Pad9 | face of Pad10]
  Pocket44: profile Sketch127, direction (1, 0, 0), length 1.6
  Sketch128 on start face of Pad10, origin (0, 0, 0), H (0, 1, 0), V (0, 0, 1)
  Pocket45: profile Sketch128, direction (-1, 0, 0), through (limit type 6)
  Fillet103: radius 0.1, on end face of Pocket39 (x2); edge [face of Pocket43 | face of Pocket39 from Sketch120.L2]; edge [face of Fillet102 | face of Pocket43]; edge [face of Pocket43 | face of Pocket39 from Sketch120.A2]; edge [face of Fillet102 | end face of Pocket40]; edge [face of Pocket39 from Sketch120.L4 | end face of Pocket40]
  Fillet104: radius 0.1, on edge [face of Hole6 | face of Hole10]; face of Hole10 (x2)
  Fillet105: radius 0.1, on edge [face of Pocket4 from Sketch9.A1 | face of Pocket43]; edge [face of Pocket43 | face of Pad2]; edge [face of Pocket43 | face of Pocket3]; edge [face of Pocket43 | face of Pad5 from Sketch7.A1]; edge [face of Pocket43 | face of Pocket44]
  Fillet106: radius 0.1, on edge [face of Pocket43 | face of Pocket1 from Sketch2.A3]; edge [face of Pocket5 from Sketch10.L1 | face of Pocket43]; edge [face of Pocket5 from Sketch10.A1 | face of Pocket43]
  Fillet107: radius 0.1, on face of Hole11; face of Hole1
  Fillet108: radius 0.1, on edge [face of Pocket43 | face of Pad3 from Sketch4.L4]; edge [face of Pad1 from Sketch1.A1 | face of Pocket43]; face of Hole12 (x2)
  Fillet109: radius 0.3, on edge [face of Pocket38 from Sketch119.A4 | face of Pocket38 from Sketch119.L23]; edge [face of Pocket38 from Sketch119.L20 | face of Pocket38 from Sketch119.A4]; edge [face of Pocket38 from Sketch119.E27 | face of Pocket38 from Sketch119.L20]; edge [face of Pocket38 from Sketch119.L23 | face of Pocket38 from Sketch119.E27]
  Fillet110: radius 0.3, on edge [face of Pocket38 from Sketch119.L19 | face of Pocket38 from Sketch119.L26]; edge [face of Pocket38 from Sketch119.L25 | face of Pocket38 from Sketch119.E27]; edge [face of Pocket38 from Sketch119.E27 | face of Pocket38 from Sketch119.L24]; edge [face of Pocket38 from Sketch119.L24 | face of Pocket38 from Sketch119.A5]; edge [face of Pocket38 from Sketch119.L21 | face of Pocket38 from Sketch119.L27]; edge [face of Pocket38 from Sketch119.E27 | face of Pocket38 from Sketch119.L21]; edge [face of Pocket38 from Sketch119.L22 | face of Pocket38 from Sketch119.E27]; edge [face of Pocket38 from Sketch119.L27 | face of Pocket38 from Sketch119.L22]
  Fillet111: radius 0.1, on end face of Pocket38 (x3); edge [face of Pocket43 | face of Pocket38 from Sketch119.L22]; edge [face of Pocket43 | face of Pocket38 from Sketch119.E27] (x2)
  Fillet112: radius 0.1, on edge [face of Pocket40 from Sketch121.L21 | face of Pocket38 from Sketch119.L16]; edge [face of Pocket38 from Sketch119.L16 | end face of Pocket40]; edge [face of Pocket38 from Sketch119.L16 | face of Pocket40 from Sketch121.L18]
  Fillet113: radius 0.1, on edge [face of Pocket40 from Sketch121.L21 | end face of Pocket40]
  Fillet114: radius 0.1, on edge [face of Pocket40 from Sketch121.A11 | end face of Pocket40]; edge [face of Pocket40 from Sketch121.A10 | end face of Pocket40]; edge [face of Pocket40 from Sketch121.E33 | end face of Pocket40]; edge [face of Pocket40 from Sketch121.A8 | end face of Pocket40]; edge [face of Pocket40 from Sketch121.L18 | end face of Pocket40]
  Fillet115: radius 0.1, on edge [face of Pocket43 | face of Pocket40 from Sketch121.L18]; edge [face of Pocket43 | face of Pocket40 from Sketch121.A8]; edge [face of Pocket43 | face of Pocket40 from Sketch121.E33]; edge [face of Pocket43 | face of Pocket40 from Sketch121.A9]; edge [face of Pocket43 | face of Pocket40 from Sketch121.A11]; edge [face of Pocket43 | face of Pocket40 from Sketch121.A12]
  Fillet116: radius 0.1, on edge [face of Pad1 from Sketch1.A1 | face of Pocket43]; edge [face of Pocket7 from Sketch13.L1 | face of Pocket43]; edge [face of Pad1 from Sketch1.A1 | face of Pocket7 from Sketch13.L1]; face of Hole7 (x2)
  Fillet117: radius 0.1, on end face of Pocket38; edge [face of Pocket43 | face of Pocket38 from Sketch119.E16] (x2); edge [face of Fillet98 | end face of Pocket40]; edge [face of Pocket38 from Sketch119.L13 | face of Pocket40 from Sketch121.L17]
  Fillet118: radius 0.1, on end face of Pocket38; edge [face of Pocket40 from Sketch121.L14 | end face of Pocket40]; edge [face of Pocket43 | face of Pocket40 from Sketch121.E31]; edge [face of Pocket40 from Sketch121.A7 | end face of Pocket40]; edge [face of Pocket40 from Sketch121.L17 | end face of Pocket40]; edge [face of Pocket43 | face of Pocket40 from Sketch121.L17]; edge [face of Pocket43 | face of Pocket40 from Sketch121.A7]; edge [face of Pocket40 from Sketch121.E31 | end face of Pocket40]; edge [face of Pocket40 from Sketch121.E31 | face of Pocket40 from Sketch121.L14]; edge [face of Pocket40 from Sketch121.L12 | face of Pocket40 from Sketch121.E31]; edge [face of Pocket43 | face of Pocket40 from Sketch121.L12]; edge [face of Pocket40 from Sketch121.L12 | end face of Pocket40]
  Fillet119: radius 0.1, on edge [face of Pocket38 from Sketch119.L8 | end face of Pocket40]
  Fillet120: radius 0.1, on end face of Pocket38 (x3); edge [face of Pocket43 | face of Pocket38 from Sketch119.E7] (x2); face of Hole8 (x2)
  Fillet121: radius 0.1, on end face of Pocket38; edge [face of Fillet73 | end face of Pocket40]; face of Hole9 (x2)
  Fillet122: radius 0.1, on edge [face of Pad37 from Sketch107.L2 | face of Pad35]; edge [face of Pad37 from Sketch107.L2 | face of Slot8]; edge [face of Slot8 | face of Pad37 from Sketch107.L2]
  Fillet123: radius 0.1, on edge [face of Pad37 from Sketch107.L2 | face of Chamfer29]
  Fillet124: radius 0.1, on edge [face of Slot8 | face of Pocket16]
  Fillet125: radius 0.1, on edge [face of Pad37 from Sketch107.L2 | face of Pocket16]
  Fillet126: radius 0.05, on edge [face of Chamfer29 | face of Pad35]
  Fillet127: radius 0.05, on edge [face of Pad37 from Sketch107.E4 | face of Chamfer29]
  Fillet128: radius 0.05, on edge [face of Pad35 | face of Slot8]; edge [face of Slot8 | face of Slot8]
  Fillet129: radius 0.01, on edge [face of Pad38 from Sketch108.E12 | face of Fillet124]
  Fillet130: radius 0.1, on edge [face of Pocket16 | face of Pad29 from Sketch61.A1]
  Fillet131: radius 1, on edge [face of Pocket43 | face of Pocket41 from Sketch124.L15]; edge [face of Pocket43 | face of Pocket41 from Sketch124.L11]; edge [face of Pocket43 | face of Pocket41 from Sketch124.L7]; edge [face of Pocket43 | face of Pocket41 from Sketch124.L3]; edge [face of Mirror3 | face of Pocket43] (x4)
  Fillet132: radius 0.1, on end face of Pocket41 (x4); face of Mirror3 (x14); edge [face of Pocket43 | face of Mirror3] (x3); edge [face of Mirror3 | face of Pocket43]; edge [face of Pocket43 | face of Pocket41 from Sketch124.L1]; edge [face of Pocket43 | face of Pocket41 from Sketch124.L2]; edge [face of Pocket43 | face of Pocket41 from Sketch124.L8]; edge [face of Pocket43 | face of Pocket41 from Sketch124.L5]; edge [face of Pocket43 | face of Pocket41 from Sketch124.L6]; face of Pocket41 from Sketch124.L4; face of Pocket41 from Sketch124.L2; face of Pocket41 from Sketch124.L6; face of Pocket41 from Sketch124.L8; face of Pocket41 from Sketch124.L10; face of Pocket41 from Sketch124.L9; face of Pocket41 from Sketch124.L12; face of Pocket41 from Sketch124.L14; face of Pocket41 from Sketch124.L13; face of Pocket41 from Sketch124.L16
  Line2: type PtPt, FirstPoint vertex [face of Slot2 | face of Slot2 | face of Chamfer27], SecondPoint {point type OnCurve, Support edge [face of Slot2 | face of Slot2], Length 0.002}
  Line3: type PtPt, FirstPoint vertex [face of Slot2 | face of Slot2 | face of Chamfer27], SecondPoint vertex of Line2
  Fill3: Boundary (edge [face of Slot2 | face of Chamfer27]; Line3; Line2)
  SewSurface3: SplitPlane Fill3
  Sketch129 on end face of Pad48, origin (2.6, 0, 0), H (0, 1, 0), V (0, 0, 1)
    projected line E1 (15.7785, 10.8) -> (15.7785, -36.4253) from edge [face of Pad48 | end face of Pad48]
    projected line E2 (15.7785, -36.028) -> (15.7785, -36.4253) from edge [face of Pad48 | end face of Pad48]
    point P2 (15.7785, -36.4253)
    projected line E3 (15.7785, -36.4253) -> (15.8587, -36.0449) from edge [face of Pad48 | end face of Pad48]
    point P3 (15.7785, -36.4253)
    line L1 (15.8587, -36.0449) -> (15.7785, -36.028)
    point P5 (15.7785, -36.028)
    perpendicularity: L1 E3
    coincidence: P5 E1, P2 P3
  Pocket46: profile Sketch129, direction (-1, 0, 0), length 1
  Fillet133: radius 0.1, on edge [face of Pad48 | end face of Pad48] (x11); edge [face of Pad48 | face of Chamfer33]; edge [face of Pad48 | face of Chamfer32]
  Fillet134: radius 0.1, on edge [face of Pocket46 | face of Pad48]; face of Pad48
  Chamfer34: length 1.8, angle 27.5, on edge [end face of Pad34 | face of Pad34 from Sketch96.L2]
  Plane9: type Offset, RefPlane face of Chamfer24, Offset 0.375, reversed
  Plane10: type Angle, RefPlane Plane9, Direction {line type PtPt, FirstPoint vertex [face of Pad17 from Sketch31.A1 | face of Chamfer24 | end face of Pad17], SecondPoint vertex [end face of Pad17 | face of Chamfer24 | face of Pad16 from Sketch30.E12]}, Angle 90
  Plane11: type Offset, RefPlane Plane10, Offset -1.9
  Sketch130 on Plane11, origin (-6.4702, 2.3133, 2.9331), H (-0.3367, -0.9416, 0), V (0.3697, -0.1322, 0.9197)
  Pocket47: profile Sketch130, direction (0.866, -0.3096, -0.3926), length 3
  Fillet135: radius 0.5, on edge [face of Pad16 from Sketch30.E12 | face of Chamfer24]
  Fillet136: radius 0.5, on edge [face of Pad17 from Sketch31.A1 | face of Chamfer24]
  Fillet137: radius 0.5, on edge [face of Chamfer24 | end face of Pad17]; edge [face of Chamfer16 | end face of Pad17]; edge [end face of Pad17 | face of Pad16 from Sketch30.E12]; edge [face of Pad17 from Sketch31.A1 | face of Chamfer16]; edge [face of Pad16 from Sketch30.E12 | face of Chamfer16]
  Fillet138: radius 0.1, on edge [face of Pad13 | face of Chamfer24]; edge [face of Pad13 | face of Chamfer16]
  Fillet139: radius 0.5, on edge [face of Chamfer15 | face of Pad13]
  Chamfer35: length 0.018, angle 27.5, on edge [face of Pad16 from Sketch30.E12 | face of Pad16 from Sketch30.L3]
  Fillet140: radius 0.01, on edge [face of Chamfer35 | face of Pad16 from Sketch30.E12]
